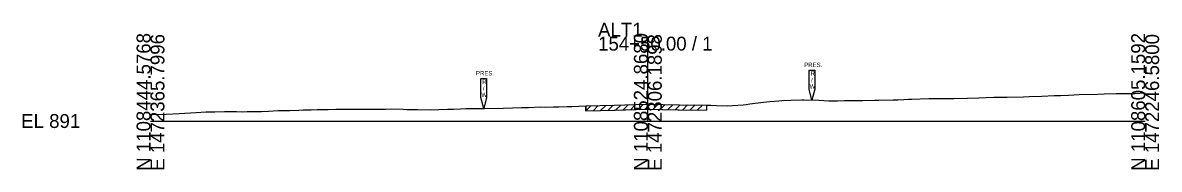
# Model space of a CAD drawing. Extents: x -26 to 2203, y -10 to 19568.
# Drawn here: x -25.7 to 202.8, y 16490.3 to 16519.8 of the extents above; entities that cross this region are included whole.
import ezdxf

# ---------------------------------------------------------------- set-up
doc = ezdxf.new("R2010")
doc.units = 0
for name, color, linetype in [('RD_GPK_XS_Cell', 7, 'Continuous'), ('RD_XS_ExGround', 7, 'Continuous'), ('RD_XS_ExPaveRet', 7, 'Continuous'), ('RD_XS_ExRW', 7, 'Continuous')]:
    doc.layers.add(name, color=color, linetype=linetype)

msp = doc.modelspace()

# ---------------------------------------------------------------- linework, layer by layer
at = {"layer": 'RD_GPK_XS_Cell'}
for p, q in [((100, 16500), (100, 16516.95)), ((0, 16500), (100, 16500)), ((100, 16500), (200, 16500))]:
    msp.add_line(p, q, dxfattribs=at)
at = {"layer": 'RD_XS_ExGround'}
msp.add_lwpolyline([(0, 16501.28), (3.17, 16501.37), (5.77, 16501.53), (9.19, 16501.72), (11.11, 16501.84), (12.95, 16501.88), (14.85, 16501.89), (17.31, 16501.91), (18.59, 16501.87), (19.46, 16501.9), (20.63, 16501.92), (21.6, 16501.92), (22.32, 16501.93), (23.75, 16501.95), (25.67, 16502.12), (26.06, 16502.14), (28.04, 16502.13), (29.8, 16502.19), (30.7, 16502.22), (32.32, 16502.28), (33.53, 16502.29), (34.47, 16502.31), (35.73, 16502.34), (37.27, 16502.36), (41, 16502.36), (41.7, 16502.37), (44.74, 16502.39), (45.19, 16502.4), (45.8, 16502.4), (47.34, 16502.36), (48.48, 16502.42), (50.83, 16502.36), (51.62, 16502.32), (52.21, 16502.32), (53.77, 16502.3), (56.2, 16502.28), (59.69, 16502.38), (60.2, 16502.39), (60.9, 16502.41), (62.35, 16502.45), (63.42, 16502.49), (65.93, 16502.52), (67.16, 16502.52), (70.96, 16502.59), (74.63, 16502.71), (75.99, 16502.75), (78.37, 16502.82), (79.5, 16502.81), (81.03, 16502.85), (81.65, 16502.85), (82.11, 16502.88), (83.79, 16502.93), (84.71, 16502.9), (87.51, 16503.04), (93.23, 16503.18), (99.71, 16503.36), (106.29, 16503.26), (111.82, 16503.21), (112.7, 16503.22), (113.81, 16503.14), (115.93, 16503.06), (119.14, 16503.28), (119.8, 16503.35), (120.48, 16503.48), (123.24, 16503.8), (124.53, 16503.91), (126.32, 16504.07), (126.94, 16504.12), (128.73, 16504.17), (130.97, 16504.24), (131.35, 16504.24), (134.41, 16504.19), (136.39, 16504.08), (137.4, 16504.05), (138.15, 16504.06), (139.54, 16504.12), (141.42, 16504.12), (141.89, 16504.12), (143.24, 16504.15), (145.62, 16504.2), (146.45, 16504.21), (149.36, 16504.26), (150.27, 16504.28), (151.48, 16504.34), (152.41, 16504.38), (153.1, 16504.41), (156.52, 16504.51), (156.83, 16504.51), (157.74, 16504.52), (160.57, 16504.54), (161.55, 16504.54), (164.31, 16504.6), (166.58, 16504.64), (168.04, 16504.7), (169.56, 16504.78), (171.78, 16504.81), (172.25, 16504.82), (175.52, 16504.89), (176.65, 16504.91), (179.25, 16505.01), (181.68, 16505.11), (182.99, 16505.15), (184.58, 16505.2), (186.76, 16505.34), (190.46, 16505.38), (191.75, 16505.45), (194.2, 16505.52), (196.78, 16505.52), (197.44, 16505.53), (197.93, 16505.55), (200, 16505.65)], dxfattribs=at)
at = {"layer": 'RD_XS_ExPaveRet'}
for p, q in [((87.51, 16502.05), (88.53, 16503.07)), ((87.51, 16502.05), (87.51, 16503.04)), ((87.51, 16503.04), (87.51, 16502.04)), ((89.01, 16502.08), (90.03, 16503.1)), ((90.51, 16502.12), (91.53, 16503.14)), ((92.01, 16502.16), (93.03, 16503.18)), ((93.23, 16502.18), (99.71, 16502.36)), ((93.46, 16502.19), (99.71, 16502.36)), ((93.51, 16502.19), (94.54, 16503.22)), ((95.01, 16502.23), (96.04, 16503.26)), ((96.51, 16502.27), (97.54, 16503.3)), ((98.01, 16502.31), (99.04, 16503.34)), ((99.51, 16502.35), (100.5, 16503.34)), ((99.71, 16502.36), (106.28, 16502.26)), ((99.71, 16502.36), (106.05, 16502.27)), ((101.01, 16502.34), (102, 16503.32)), ((102.51, 16502.32), (103.5, 16503.3)), ((104.01, 16502.29), (105, 16503.28)), ((105.51, 16502.27), (106.5, 16503.26)), ((107.01, 16502.25), (108, 16503.24)), ((108.51, 16502.24), (109.5, 16503.23)), ((110.01, 16502.22), (111, 16503.21)), ((111.82, 16503.21), (111.82, 16502.21)), ((111.82, 16503.21), (111.82, 16502.21)), ((87.51, 16502.05), (93.46, 16502.19)), ((87.51, 16502.04), (93.23, 16502.18)), ((87.51, 16502.05), (87.51, 16502.05)), ((106.05, 16502.27), (111.82, 16502.21)), ((106.28, 16502.26), (111.82, 16502.21))]:
    msp.add_line(p, q, dxfattribs=at)
at = {"layer": 'RD_XS_ExRW'}
for points in [[(132.45, 16510.22), (133.55, 16510.22), (133.55, 16506.39), (133, 16504.21), (132.45, 16506.39)], [(66.45, 16508.53), (67.55, 16508.53), (67.55, 16504.7), (67, 16502.51), (66.45, 16504.7)]]:
    msp.add_lwpolyline(points, close=True, dxfattribs=at)

# ---------------------------------------------------------------- texts
at = {"layer": 'RD_GPK_XS_Cell'}
for s, p in [('ALT1', (90, 16516.95)), ('154+50.00 / 1', (90, 16514.15)), ('EL 891', (-26, 16498.6))]:
    msp.add_text(s, height=2.8, dxfattribs=at).set_placement(p)
for s, p in [('N 1108444.5768', (0, 16490)), ('E 1472365.7996', (2.8, 16490)), ('N 1108524.8680', (100, 16490)), ('E 1472306.1898', (102.8, 16490)), ('N 1108605.1592', (200, 16490)), ('E 1472246.5800', (202.8, 16490))]:
    msp.add_text(s, height=2.8, rotation=90, dxfattribs=at).set_placement(p)
at = {"layer": 'RD_XS_ExRW'}
for s, p in [('PRES.', (131.45, 16510.85)), ('PRES.', (65.45, 16509.16)), ('R', (132.71, 16509.13)), ('R', (66.71, 16507.44)), ('/', (66.83, 16506.13)), ('W', (132.53, 16506.51)), ('/', (132.83, 16507.82)), ('W', (66.53, 16504.81))]:
    msp.add_text(s, height=0.875, dxfattribs=at).set_placement(p)

doc.saveas('drawing.dxf')
